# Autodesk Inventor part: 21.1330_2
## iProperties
Created: 2006-12
Part Number: 21.1330_2
Document SubType Name: Modeling
Designer: Andy Moles
Material: Steel, Mild
Density: 7.86 g/cm^3
Description: M6 SQUARE NUT POS FXG
Mass: 5.20492 g
Surface Area: 8.43697 cm^2
Volume: 0.662203 cm^3
Author: Andy Moles
Title: M6 SQUARE NUT POS FXG
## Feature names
1. Extrusion1
2. Revolution1
3. Fillet2
4. Extrusion3
